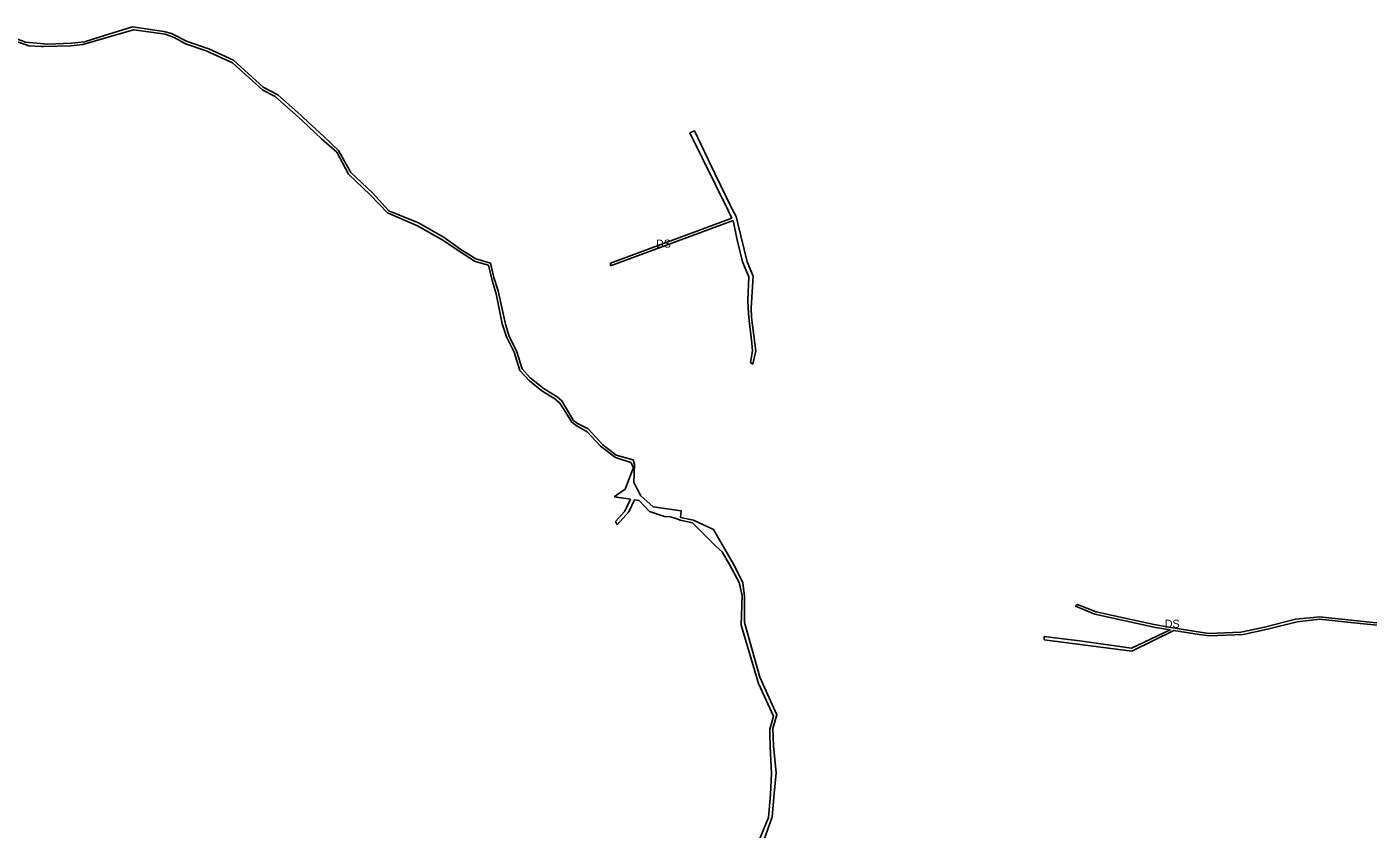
# Model space of a CAD drawing. Extents: x -477304 to -465641, y -1159113 to -1149285.
# Drawn here: x -473942 to -472433, y -1156437 to -1155536 of the extents above; entities that cross this region are included whole.
import ezdxf

# ---------------------------------------------------------------- set-up
doc = ezdxf.new("R2010")
doc.units = 0
doc.layers.add('35', color=7, linetype='Continuous')

msp = doc.modelspace()

# ---------------------------------------------------------------- linework, layer by layer
at = {"layer": '35'}
for p, q in [((-473976, -1155544.5), (-473939.4, -1155557.5)), ((-473822.8, -1155536.1), (-473860.1, -1155547.7)), ((-473787.6, -1155541.2), (-473822.8, -1155536.1)), ((-473821.7, -1155539.3), (-473813, -1155540.6)), ((-473813, -1155540.6), (-473785.9, -1155544.5)), ((-473778.9, -1155543.4), (-473787.6, -1155541.2)), ((-473761.4, -1155552.4), (-473778.9, -1155543.4)), ((-473923.2, -1155558.2), (-473892, -1155557.6)), ((-473763.2, -1155555.3), (-473740, -1155563.1)), ((-473736.9, -1155560.8), (-473761.4, -1155552.4)), ((-473740, -1155563.1), (-473710.2, -1155576.6)), ((-473709.2, -1155573.5), (-473736.9, -1155560.8)), ((-473675.7, -1155603.7), (-473709.2, -1155573.5)), ((-473659.5, -1155612.6), (-473675.7, -1155603.7)), ((-473631.6, -1155641.6), (-473610.3, -1155661.8)), ((-473191, -1155652.9), (-473196.2, -1155655.2)), ((-473167.9, -1155700.9), (-473191, -1155652.9)), ((-473196.2, -1155655.2), (-473153.2, -1155742.6)), ((-473553.1, -1155722.4), (-473577.4, -1155699.9)), ((-473579.9, -1155701.7), (-473555.5, -1155725)), ((-473148.5, -1155740.9), (-473167.9, -1155700.9)), ((-473555.5, -1155725), (-473536.1, -1155745.1)), ((-473536.1, -1155745.1), (-473502.4, -1155759.7)), ((-473153.2, -1155742.6), (-473148.9, -1155751)), ((-473144, -1155749), (-473148.5, -1155740.9)), ((-473472.3, -1155772.8), (-473501.1, -1155756.4)), ((-473148.9, -1155751), (-473285.4, -1155801.6)), ((-473285.2, -1155804.4), (-473147.5, -1155753.8)), ((-473142.1, -1155757.1), (-473144, -1155749)), ((-473131.8, -1155800.1), (-473142.1, -1155757.1)), ((-473453.5, -1155786.3), (-473472.3, -1155772.8)), ((-473436.8, -1155796.8), (-473453.5, -1155786.3)), ((-473437.5, -1155799.8), (-473422.6, -1155803.8)), ((-473420.3, -1155801.5), (-473436.8, -1155796.8)), ((-473422.6, -1155803.8), (-473418.4, -1155820.9)), ((-473416.5, -1155817.8), (-473420.3, -1155801.5)), ((-473285.4, -1155801.6), (-473285.2, -1155804.4)), ((-473124.9, -1155816.1), (-473131.8, -1155800.1)), ((-473411.6, -1155832.8), (-473416.5, -1155817.8)), ((-473127.3, -1155851.9), (-473124.9, -1155816.1)), ((-473130.9, -1155843.2), (-473130.5, -1155851.7)), ((-473126.9, -1155862.6), (-473127.3, -1155851.9)), ((-473126.5, -1155891.5), (-473125.5, -1155899.9)), ((-473125.5, -1155899.9), (-473128.1, -1155913.3)), ((-473128.1, -1155913.3), (-473125.3, -1155915.2)), ((-473345.3, -1155951.9), (-473360.1, -1155942.6)), ((-473347.9, -1155954.1), (-473342.4, -1155959)), ((-473340.2, -1155956.3), (-473345.3, -1155951.9)), ((-473332.5, -1155968.9), (-473340.2, -1155956.3)), ((-473342.4, -1155959), (-473335.6, -1155969.5)), ((-473335.6, -1155969.5), (-473329, -1155980.2)), ((-473326.9, -1155978.5), (-473332.5, -1155968.9)), ((-473329, -1155980.2), (-473324, -1155984.1)), ((-473322.3, -1155981.8), (-473326.9, -1155978.5)), ((-473324, -1155984.1), (-473311.7, -1155990.9)), ((-473279.9, -1156020), (-473262.4, -1156025.7)), ((-473259.5, -1156031.3), (-473269, -1156055.4)), ((-473262.4, -1156025.7), (-473259.5, -1156031.3)), ((-473258.2, -1156027.4), (-473259.9, -1156022.7)), ((-473259, -1156048.1), (-473258.2, -1156027.4)), ((-473269, -1156055.4), (-473281.2, -1156064.2)), ((-473281.2, -1156064.2), (-473262.8, -1156066.9)), ((-473262.8, -1156066.9), (-473269.2, -1156080.2)), ((-473264.7, -1156080.9), (-473258.4, -1156067.5)), ((-473258.4, -1156067.5), (-473253, -1156068.2)), ((-473269.2, -1156080.2), (-473279.9, -1156091.7)), ((-473279.9, -1156091.7), (-473278, -1156095.6)), ((-473278, -1156095.6), (-473264.7, -1156080.9)), ((-473224.6, -1156086.2), (-473218, -1156086.5)), ((-473218, -1156086.5), (-473209.8, -1156089.2)), ((-473209.8, -1156089.2), (-473207, -1156090.2)), ((-473207, -1156090.2), (-473193.2, -1156093.2)), ((-473191.9, -1156090.2), (-473206.7, -1156087.4)), ((-473193.2, -1156093.2), (-473166.1, -1156120.4)), ((-473166.1, -1156120.4), (-473159.7, -1156126)), ((-473159.7, -1156126), (-473151.4, -1156140.2)), ((-473145.6, -1156142.5), (-473152.6, -1156130)), ((-473151.4, -1156140.2), (-473140.7, -1156160.3)), ((-472739.3, -1156193.3), (-472760.1, -1156184.9)), ((-472701.7, -1156201.5), (-472739.3, -1156193.3)), ((-473138.3, -1156208.4), (-473119, -1156273.9)), ((-472673.9, -1156207.6), (-472701.7, -1156201.5)), ((-472546.5, -1156212.8), (-472513.1, -1156204.6)), ((-472438.5, -1156204), (-472488.5, -1156198.9)), ((-472797.7, -1156221), (-472797.8, -1156224.9)), ((-472797.8, -1156224.9), (-472699.2, -1156237.6)), ((-472755.1, -1156226.4), (-472797.7, -1156221)), ((-472699.5, -1156234), (-472755.1, -1156226.4)), ((-472623.4, -1156218.6), (-472612, -1156220.3)), ((-473098.2, -1156309.1), (-473117.5, -1156266.5)), ((-473102.7, -1156324.5), (-473098.2, -1156309.1)), ((-473106.3, -1156325), (-473106.1, -1156330.1)), ((-473102.1, -1156344), (-473102.7, -1156324.5))]:
    msp.add_line(p, q, dxfattribs=at)
for points in [[(-473891.5, -1155554.4), (-473917.8, -1155555.4), (-473943.2, -1155553.3), (-473973.8, -1155541.7), (-473995.2, -1155536.5)], [(-473892, -1155557.6), (-473878.5, -1155556.1), (-473821.7, -1155539.3)], [(-473860.1, -1155547.7), (-473876.9, -1155553), (-473891.5, -1155554.4)], [(-473785.9, -1155544.5), (-473775.9, -1155548.1), (-473763.2, -1155555.3)], [(-473939.4, -1155557.5), (-473925.5, -1155558.1), (-473923.2, -1155558.2)], [(-473710.2, -1155576.6), (-473676.1, -1155607.4), (-473662.5, -1155614.2), (-473631.6, -1155641.6)], [(-473631, -1155637.9), (-473633.7, -1155635.5), (-473659.5, -1155612.6)], [(-473577.4, -1155699.9), (-473591.1, -1155675), (-473607.7, -1155659.4), (-473631, -1155637.9)], [(-473610.3, -1155661.8), (-473593.2, -1155676.9), (-473579.9, -1155701.7)], [(-473501.1, -1155756.4), (-473534.7, -1155742.8), (-473553.1, -1155722.4)], [(-473502.4, -1155759.7), (-473474, -1155775.9), (-473455.6, -1155788.2), (-473437.5, -1155799.8)], [(-473147.5, -1155753.8), (-473143.2, -1155773.7), (-473136.8, -1155800), (-473129.7, -1155816.8), (-473130.9, -1155843.2)], [(-473418.4, -1155820.9), (-473414, -1155835.9), (-473407.1, -1155869.9)], [(-473399.1, -1155883.8), (-473403.4, -1155870.2), (-473411.6, -1155832.8)], [(-473130.5, -1155851.7), (-473129.9, -1155863), (-473126.5, -1155891.5)], [(-473125.3, -1155915.2), (-473122.1, -1155900.2), (-473126.9, -1155862.6)], [(-473407.1, -1155869.9), (-473402.3, -1155884.2), (-473393.5, -1155901.5), (-473387.1, -1155922.2), (-473376.4, -1155933.8), (-473362.6, -1155945), (-473347.9, -1155954.1)], [(-473360.1, -1155942.6), (-473375.5, -1155930.5), (-473384.7, -1155920.2), (-473391.1, -1155900), (-473399.1, -1155883.8)], [(-473259.9, -1156022.7), (-473278.9, -1156017.4), (-473294, -1156005.7), (-473310.5, -1155987.7), (-473322.3, -1155981.8)], [(-473311.7, -1155990.9), (-473296.4, -1156007.2), (-473279.9, -1156020)], [(-473237.3, -1156075.3), (-473251.2, -1156062.8), (-473259, -1156048.1)], [(-473253, -1156068.2), (-473241.5, -1156080.4), (-473224.6, -1156086.2)], [(-473206.7, -1156087.4), (-473205.9, -1156079.8), (-473237.3, -1156075.3)], [(-473152.6, -1156130), (-473169.5, -1156100.9), (-473191.9, -1156090.2)], [(-473134.5, -1156176.2), (-473136.5, -1156160.8), (-473145.6, -1156142.5)], [(-473140.7, -1156160.3), (-473137.3, -1156175), (-473138.3, -1156208.4)], [(-473117.5, -1156266.5), (-473134.8, -1156205.2), (-473134.5, -1156176.2)], [(-472760.1, -1156184.9), (-472762.5, -1156187.1), (-472740.7, -1156195.9), (-472672.4, -1156210.9)], [(-472388.4, -1156195.1), (-472405.1, -1156203.9), (-472424.3, -1156205.5), (-472438.5, -1156204)], [(-472672.4, -1156210.9), (-472655.9, -1156213.6), (-472699.5, -1156234)], [(-472629.4, -1156215.1), (-472655.2, -1156211), (-472673.9, -1156207.6)], [(-472612, -1156220.3), (-472574.1, -1156218.9), (-472546.5, -1156212.8)], [(-472488.5, -1156198.9), (-472495, -1156199.5), (-472515, -1156201.4), (-472550, -1156210.5), (-472576.8, -1156216.3)], [(-472513.1, -1156204.6), (-472488.3, -1156201.6), (-472442.5, -1156206.3), (-472422.5, -1156208.4)], [(-472699.2, -1156237.6), (-472651.8, -1156214.1), (-472623.4, -1156218.6)], [(-472576.8, -1156216.3), (-472612.6, -1156217.7), (-472629.4, -1156215.1)], [(-473119, -1156273.9), (-473102.1, -1156310.6), (-473106.3, -1156325)], [(-473106.1, -1156330.1), (-473105.7, -1156345.1), (-473104.2, -1156374.4)], [(-473101.2, -1156397.4), (-473099.2, -1156374.3), (-473102.1, -1156344)], [(-473104.2, -1156374.4), (-473105.6, -1156398.4), (-473107.7, -1156424.5)], [(-473113, -1156450.3), (-473103.5, -1156423.7), (-473101.2, -1156397.4)], [(-473107.7, -1156424.5), (-473118.2, -1156449.7), (-473113.4, -1156460.2)]]:
    msp.add_lwpolyline(points, dxfattribs=at)

# ---------------------------------------------------------------- texts
for p in [(-473234.1, -1155784.1), (-472662.1, -1156211.2)]:
    msp.add_text('DS', height=9, dxfattribs=at).set_placement(p)

doc.saveas('drawing.dxf')
